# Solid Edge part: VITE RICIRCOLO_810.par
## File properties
Subject: VITE RICIRCOLO 810
Author: f_grande
Template: Normal.par
Last saved by: f_grande
Revision: 6
Application: Solid Edge
Material: Acciaio
Stile della faccia: Acciaio
Stile di riempimento: ANSI32(Acciaio)
Stile virtuale: Acciaio lavorato a macchina
Coef. of Thermal Exp: 0.0
Thermal Conductivity: 32.0
Specific Heat: 481.0
Modulus of Elasticity: 199947953000.0
Poisson's Ratio: 0.29
Yield Stress: 262000766.0
Ultimate Stress: 358527364.0
Elongation: 0.0
Tipo di contenuto documento: 0
Densità: 7833,000 kg/m^3
Precisione: 0,990
Document Number: KR0121
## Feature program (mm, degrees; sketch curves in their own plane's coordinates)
sketch for "unnamed Protrusion 1" plane through (0, 0, 0) normal (0, -1, 0) x-axis (1, 0, 0)
  circle centre (0, 0) radius 8
extrude "unnamed Protrusion 1" add finite 810 along -normal
sketch for "ExtrudedCutout_1" #1 plane through (0, 0, 0) normal (0, -1, 0) x-axis (1, 0, 0)
  circle centre (0, 0) radius 5
sketch for "ExtrudedCutout_1" #2 plane through (0, 0, 0) normal (0, -1, 0) x-axis (1, 0, 0)
  circle centre (0, 0) radius 9.8339
extrude "ExtrudedCutout_1" cut finite 12 along -normal
sketch for "unnamed RevolvedCutout 1" plane through (0, 0, 0) normal (1, 0, 0) x-axis (0, 1, 0)
  line (3, 5) -> (4.1, 5)
  line (4.1, 5) -> (4.1, 4.6)
  line (4.1, 4.6) -> (3, 4.6)
  line (3, 4.6) -> (3, 5)
  dimension (linear) = 3
  dimension (linear) = 4.1
revolve "unnamed RevolvedCutout 1" cut full turn 360 deg
helix cutout "HelixCutout_2"  Pitch = 5 mm
sketch for "ExtrudedCutout_2" #1 plane through (0, 810, 0) normal (0, 1, 0) x-axis (-1, 0, 0)
  circle centre (0, 0) radius 6
sketch for "ExtrudedCutout_2" #2 plane through (0, 810, 0) normal (0, 1, 0) x-axis (-1, 0, 0)
  circle centre (0, 0) radius 9.9648
extrude "ExtrudedCutout_2" cut finite 54 along -normal
sketch for "ExtrudedCutout_3" #1 plane through (0, 810, 0) normal (0, 1, 0) x-axis (-1, 0, 0)
  circle centre (0, 0) radius 5
sketch for "ExtrudedCutout_3" #2 plane through (0, 810, 0) normal (0, 1, 0) x-axis (-1, 0, 0)
  circle centre (0, 0) radius 10.6518
extrude "ExtrudedCutout_3" cut finite 16 along -normal
thread "Filettatura_3"  ThreadDepth = 16 mm
chamfer "Smusso_1" setback 1
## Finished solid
Body 1: solid body, 18 faces, 20 edges, 4 vertices.
  Faces by surface: plane 9, cylinder 7, cone 1, spline 1
  Edges by curve: circle 16, line 2, spline 2
Bounding box of the edges (mm; curved faces can reach further): 16.000 x 810.000 x 16.000, from (-8, 0, -8) to (8, 810, 8).
Cylindrical faces by radius (mm): R4.6 x1, R5 x3, R6 x2, R8 x1
Conical faces (half-angle, radius in mm at the cone's reference point): 45 deg R5 x1
Planar faces by outward normal: +x 1, +y 4, -x 1, -y 3
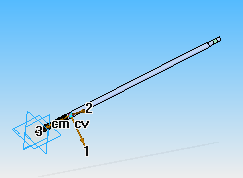
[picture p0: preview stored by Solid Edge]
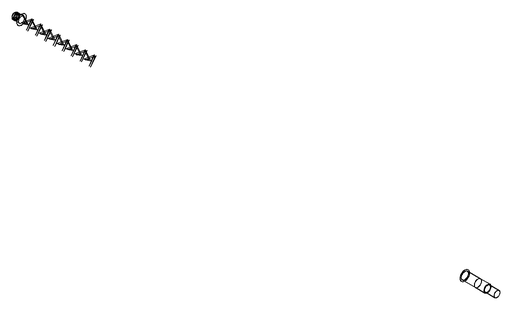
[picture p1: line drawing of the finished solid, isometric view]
